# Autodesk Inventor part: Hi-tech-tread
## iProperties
Created: 2010-10
Part Number: Hi-tech-tread
Document SubType Name: Modeling
Designer: Administrator
Density: 1.28 g/cm^3
Material: Thermoplastic Resin
Mass: 355.84 g
Surface Area: 434.623 cm^2
Volume: 278 cm^3
Author: Administrator
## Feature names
1. Base1
